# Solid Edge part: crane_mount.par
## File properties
Author: Haley
Template: Metric Part.par
Last saved by: Lee
Revision: 7
Application: Solid Edge
Accuracy: 0.990
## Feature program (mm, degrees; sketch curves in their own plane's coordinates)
sketch for "unnamed Protrusion 1" plane through (0, 0, 0) normal (0, -1, 0) x-axis (1, 0, 0)
  line (76.2, -3.8) -> (76.2, 76.2)
  line (76.2, 76.2) -> (-76.2, 76.2)
  line (-76.2, 76.2) -> (-76.2, -3.8)
  line (-76.2, -3.8) -> (76.2, -3.8)
extrude "unnamed Protrusion 1" add finite 25.4 symmetric
fillet "Round_1" radius 25.4
sketch for "Hole_1" plane through (0, -12.7, 38.1) normal (0, -1, 0) x-axis (1, 0, 0)
  hole centre (0, 0) bore radius 19.05
hole "Hole_1" diameter 38.1 through
fillet "Round_2" radius 5
sketch for "ExtrudedCutout_1" plane through (0, 0, 0) normal (1, 0, 0) x-axis (0, 1, 0)
  circle centre (0, -875.4) radius 875.4
extrude "ExtrudedCutout_1" cut finite 152.4 symmetric
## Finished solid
Body 1: solid body, 19 faces, 42 edges, 24 vertices.
  Faces by surface: cylinder 10, plane 5, torus 4
  Edges by curve: circle 20, line 18, intersection 4
Bounding box of the edges (mm; curved faces can reach further): 152.400 x 25.400 x 76.292, from (-76.2, -12.7, -0.0921) to (76.2, 12.7, 76.2).
Cylindrical faces by radius (mm): R5 x6, R19.05 x1, R25.4 x2, R875.4 x1
Toroidal faces (ring radius, tube radius in mm): R20.4 r5 x4
Planar faces by outward normal: +x 1, +y 1, +z 1, -x 1, -y 1
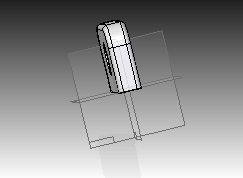
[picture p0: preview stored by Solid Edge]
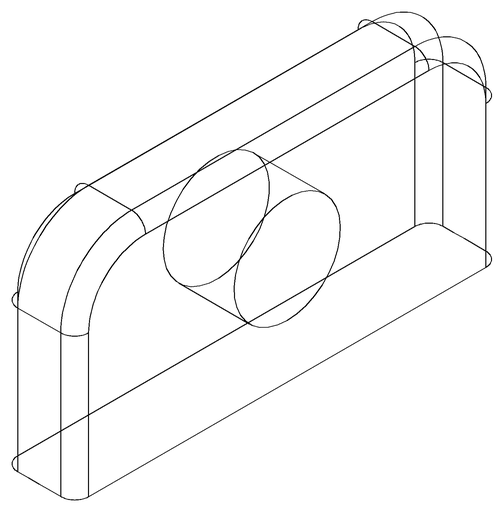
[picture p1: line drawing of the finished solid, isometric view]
